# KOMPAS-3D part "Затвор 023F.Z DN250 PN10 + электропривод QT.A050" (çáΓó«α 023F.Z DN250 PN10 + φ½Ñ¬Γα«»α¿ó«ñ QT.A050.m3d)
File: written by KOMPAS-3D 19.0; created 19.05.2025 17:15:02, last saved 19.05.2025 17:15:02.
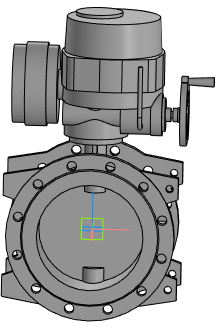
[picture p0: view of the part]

Document properties: Полное имя файла: Затвор 023F.Z DN250 PN10 + электропривод QT.A050.a3d

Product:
- Part/product: Затвор 023F.Z DN250 PN10 + электропривод QT.A050
    Масса: 171.262

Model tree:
1. Операция без истории:1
